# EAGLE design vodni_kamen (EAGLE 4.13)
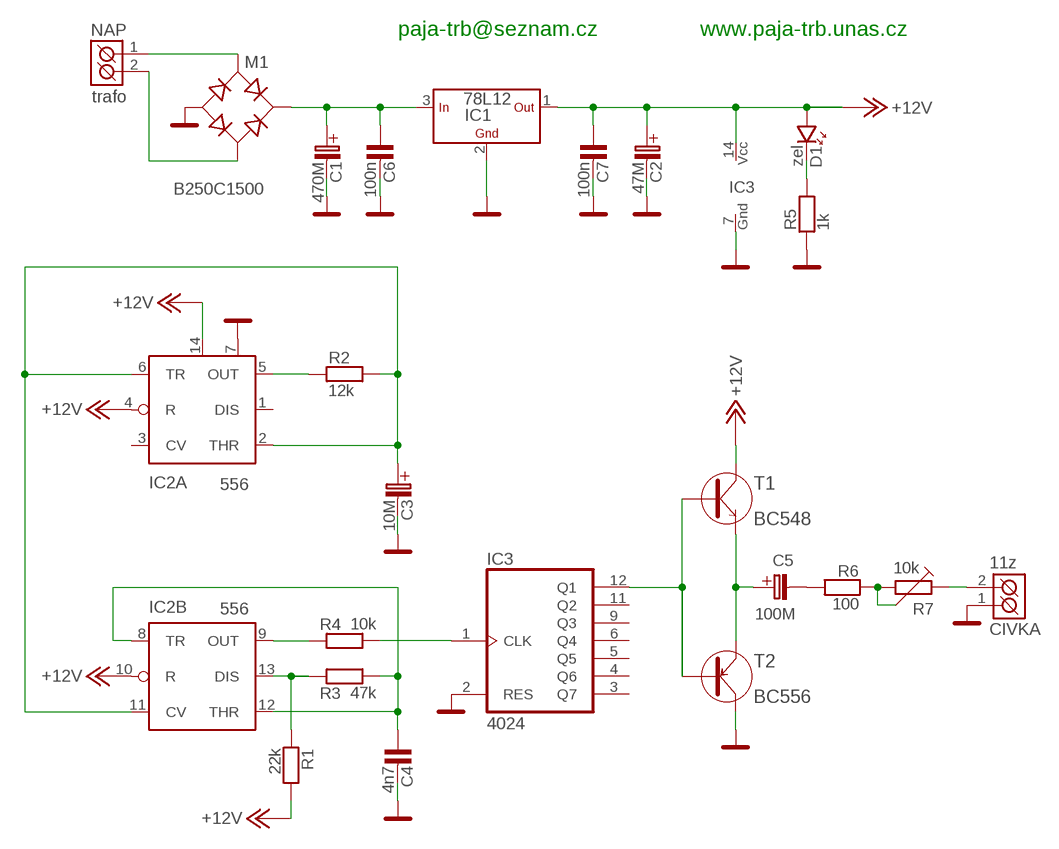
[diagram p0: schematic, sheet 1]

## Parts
C1  470M  470M/25V  [C_EL_5]
C2  47M  47M/25V  [C_EL_2]
C3  10M  10M/25V  [C_EL_2]
C4  4n7  C-5  [C-5]
C5  100M  100M/16V  [C_EL_2,5]
C6  100n  C-5  [C-5]
C7  100n  C-5  [C-5]
CIVKA  11z  ARK500/2  [ARK500/2]
D1  zel  LED_5  [LED_5]
IC1  78L12  78L  [TO-92]
IC2  556  [DIL14]
IC3  4024  [DIL14]
M1  B250C1500  [DM_WOM]
NAP  trafo  ARK500/2  [ARK500/2]
R1  22k  R-7,5@2  [R-10]
R2  12k  R-7,5  [R-7,5]
R3  47k  R-7,5@2  [R-10]
R4  10k  R-7,5@2  [R-10]
R5  1k  R-7,5  [R-7,5]
R6  100  R-7,5@3  [R-STOJ]
R7  10k  PT-10V_LEZ  [PT10V]
T1  BC548  BC546  [TO-92]
T2  BC556  [TO-92]

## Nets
+12V: C2.C+(C_EL+) C7.1 D1.A1(A) IC1.1(OUT) IC2.4(A:R) IC2.10(B:R) IC2.14(P:V+) IC3.14(VCC) R1.2 T1.1(C)
GND: C1.C-(C_EL-) C2.C-(C_EL-) C3.C-(C_EL-) C4.2 C6.2 C7.2 CIVKA.1(K1) IC1.2(GND) IC2.7(P:GND) IC3.2(RES) IC3.7(GND) M1.- R5.1 T2.1(C)
N$1: C3.C+(C_EL+) IC2.2(A:THR) IC2.6(A:TR) IC2.11(B:CV) R2.2
N$2: IC2.5(A:OUT) R2.1
N$3: IC2.9(B:OUT) R4.1
N$4: C4.1 IC2.8(B:TR) IC2.12(B:THR) R3.2
N$5: D1.K1(K) R5.2
N$6: IC2.13(B:DIS) R1.1 R3.1
N$7: C5.C+(C_EL+) T1.3(E) T2.3(E)
N$8: IC3.1(CLK) R4.2
N$9: IC3.12(Q1) T1.2(B) T2.2(B)
N$10: C1.C+(C_EL+) C6.1 IC1.3(IN) M1.+
N$11: R6.1 R7.2 R7.3
N$12: C5.C-(C_EL-) R6.2
N$13: CIVKA.2(K2) R7.1
N$17: M1.AC1 NAP.1(K1)
N$18: M1.AC2 NAP.2(K2)
Unconnected: IC2.1(A:DIS) IC2.3(A:CV) IC3.3(Q7) IC3.4(Q6) IC3.5(Q5) IC3.6(Q4) IC3.9(Q3) IC3.11(Q2)

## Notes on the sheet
- paja-trb@seznam.cz | www.paja-trb.unas.cz

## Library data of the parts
C1 = #PaJa_C-:470M/25V
C2 = #PaJa_C-:47M/25V
C3 = #PaJa_C-:10M/25V
C4 C6 C7 = #PaJa_92:C-5
C5 = #PaJa_C-:100M/16V
CIVKA NAP = #PaJa_92:ARK500/2
D1 = #PaJa_92:LED_5
IC1 = #PaJa_92:78L??
IC2 = 1_GM99:556
IC3 = 40xx:4024
M1 = #PaJa_92:B250C1500
R1 R3 R4 = #PaJa_92:R-7,5@2
R2 R5 = #PaJa_92:R-7,5
R6 = #PaJa_92:R-7,5@3
R7 = #PaJa_92:PT-10V_LEZ
T1 = #PaJa_92:BC546
T2 = #PaJa_92:BC556

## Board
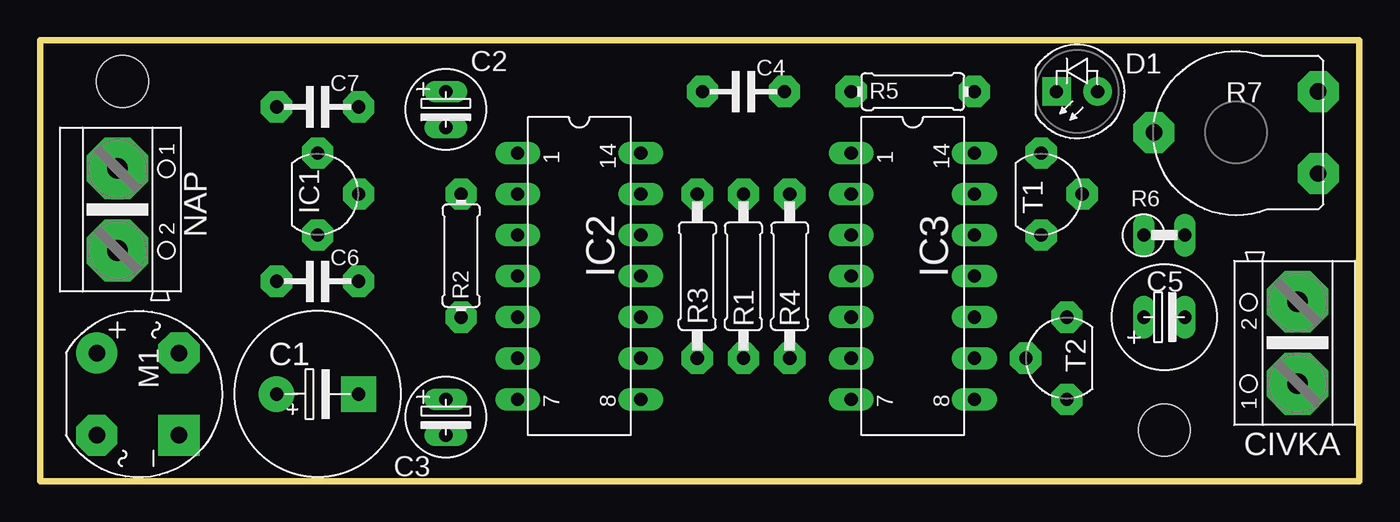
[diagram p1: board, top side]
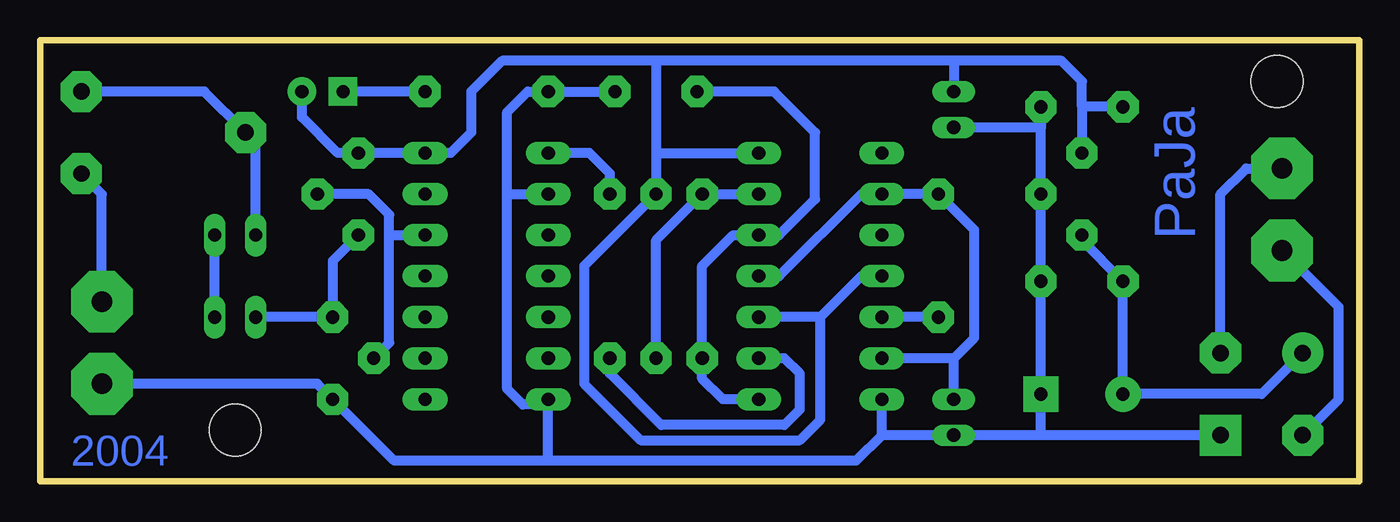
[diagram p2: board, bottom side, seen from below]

Size 81.58 x 27.3 mm. Coordinates in mm from the lower left corner, seen from the top.
Outline: 0,0 81.58,0 81.58,27.3 0,27.3 0,0
Copper layers 16: Bottom 0.035mm
Design rules "default": minimum track width 10mil, minimum drill 24mil, track to track 8mil, track to pad 8mil, pad to pad 8mil, via to via 8mil, smd to smd 8mil, copper to edge 40mil, drill to drill 8mil, minimum pad ring 10mil, minimum via ring 8mil, stop-mask expansion 4mil, vias tented up to drill 0mil, thermal gap 10mil
Holes 3.2 mm at 5.08,24.77 69.53,3.17

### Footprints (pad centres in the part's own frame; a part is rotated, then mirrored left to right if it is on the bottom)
C_EL_5 = drill 0.813 pad 2.184 round: C+ -2.54,0 | drill 0.813 pad 2.184 square: C- 2.54,0
C_EL_2 = drill 0.813 pad 1.27 long: C+ 0,0; C- 2.223,0
C-5 = drill 0.813 pad 1.93 octagon: 1 -2.54,0; 2 2.54,0
C_EL_2,5 = drill 0.813 pad 1.27 long: C+ -1.27,0; C- 1.27,0
ARK500/2 = drill 1.27 pad 3.81 octagon: 1 -2.54,0; 2 2.54,0
LED_5 = drill 0.813 pad 1.778 round: A1 -1.27,0 | drill 0.813 pad 1.778 square: K1 1.27,0
TO-92 = drill 0.813 pad 1.93 octagon: 1 0,2.54; 2 2.54,0; 3 0,-2.54
DIL14 = drill 0.813 pad 1.4 long: 1 -7.62,-3.81; 2 -5.08,-3.81; 3 -2.54,-3.81; 4 0,-3.81; 5 2.54,-3.81; 6 5.08,-3.81; 7 7.62,-3.81; 8 7.62,3.81; 9 5.08,3.81; 10 2.54,3.81; 11 0,3.81; 12 -2.54,3.81; 13 -5.08,3.81; 14 -7.62,3.81
DM_WOM = drill 1.016 pad 2.54 round: + -2.54,-2.54 | drill 1.016 pad 2.54 square: - 2.54,2.54 | drill 1.016 pad 2.54 octagon: AC1 -2.54,2.54; AC2 2.54,-2.54
R-10 = drill 0.813 pad 1.93 octagon: 1 -5.08,0; 2 5.08,0
R-7,5 = drill 0.813 pad 1.93 octagon: 1 -3.81,0; 2 3.81,0
R-STOJ = drill 0.813 pad 1.27 long: 1 -1.27,0; 2 1.27,0
PT10V = drill 1.016 pad 2.54 octagon: 1 -2.54,-5.08; 2 2.54,-5.08; 3 0,5.08

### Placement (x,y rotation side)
C1  17.14,5.4 0 top
C2  25.08,24.13 270 top
C3  25.08,5.08 270 top
C4  43.5,24.13 0 top
C5  69.53,10.16 0 top
C6  17.14,12.38 0 top
C7  17.14,23.18 0 top
CIVKA  77.79,8.57 90 top
D1  64.14,24.13 180 top
IC1  17.14,17.78 0 top
IC2  33.34,12.7 270 top
IC3  53.98,12.7 270 top
M1  6.03,5.4 270 top
NAP  4.76,16.83 270 top
R1  43.5,12.7 90 top
R2  26.04,13.97 90 top
R3  40.64,12.7 270 top
R4  46.35,12.7 90 top
R5  53.98,24.13 0 top
R6  69.53,15.24 0 top
R7  73.98,21.59 90 top
T1  61.91,17.78 0 top
T2  63.5,7.62 180 top

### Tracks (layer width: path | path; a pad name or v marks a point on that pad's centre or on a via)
+12V
  Bottom 0.61: 43.5,20.32 IC2.14 | 43.5,20.32 R1.2 47.94,13.34 47.94,6.03 44.45,2.54 34.61,2.54 33.34,3.81 33.34,10.16 | IC2.4 30.8,12.7 33.34,10.16 | 33.34,10.16 IC2.10 | 43.5,26.04 53.02,26.04 54.93,24.13 54.93,21.59 56.2,20.32 IC3.14 T1.1 61.91,20.64 62.23,20.32 63.18,20.32 65.41,22.54 D1.A1 | 25.08,26.04 43.5,26.04 | 43.5,26.04 43.5,20.32 | 25.08,26.04 C2.C+ | 25.08,26.04 18.41,26.04 17.14,24.77 17.14,23.18 | 17.14,23.18 IC1.1 | C7.1 17.14,23.18
GND
  Bottom 0.61: 50.16,1.27 IC3.7 50.48,4.76 51.75,4.76 52.7,5.71 52.7,17.78 | 29.53,2.86 IC2.7 | 50.16,1.27 59.69,1.27 T2.1 64.45,6.03 CIVKA.1 | C4.2 R5.1 51.44,24.13 52.7,22.86 52.7,17.78 | 52.7,17.78 IC3.2 | 29.53,2.86 C3.C- 19.68,2.86 | 50.16,1.27 31.11,1.27 29.53,2.86 | C2.C- 19.68,21.91 C7.2 IC1.2 C6.2 C1.C- 19.68,2.86 | M1.- 19.68,2.86
N$1
  Bottom 0.61: IC2.11 35.88,12.7 30.8,17.78 IC2.2 R2.2 23.81,15.56 23.81,8.89 25.08,7.62 | C3.C+ 25.08,7.62 | 25.08,7.62 IC2.6
N$2
  Bottom 0.61: R2.1 IC2.5
N$3
  Bottom 0.61: R4.1 46.35,6.67 43.18,3.49 35.56,3.49 34.61,4.45 34.61,6.67 35.56,7.62 IC2.9
N$4
  Bottom 0.61: 40.64,6.35 R3.2 | C4.1 36.2,24.13 33.66,21.59 33.66,17.46 35.88,15.24 IC2.12 38.73,15.24 40.64,13.34 40.64,6.35 | IC2.8 39.37,5.08 40.64,6.35
N$5
  Bottom 0.61: R5.2 D1.K1
N$6
  Bottom 0.61: IC2.13 R3.1 43.5,14.92 R1.1
N$7
  Bottom 0.61: C5.C+ T2.3 63.5,13.65 T1.3
N$8
  Bottom 0.61: R4.2 46.35,19.05 47.62,20.32 IC3.1
N$9
  Bottom 0.61: T1.2 61.28,17.78 60.01,16.51 60.01,15.24 | 60.01,15.24 60.01,8.57 T2.2 | 60.01,15.24 IC3.12
N$10
  Bottom 0.61: IC1.3 17.14,14.92 C6.1 C1.C+ 6.03,5.4 M1.+
N$11
  Bottom 0.61: R7.2 71.44,24.13 R7.3 68.26,20.95 R6.1
N$12
  Bottom 0.61: C5.C- R6.2
N$13
  Bottom 0.61: R7.1 77.79,17.78 CIVKA.2
N$17
  Bottom 0.61: NAP.1 6.99,19.37 8.57,17.78 M1.AC1
N$18
  Bottom 0.61: M1.AC2 1.27,5.08 1.27,10.79 NAP.2

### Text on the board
Bottom: PaJa | 2004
